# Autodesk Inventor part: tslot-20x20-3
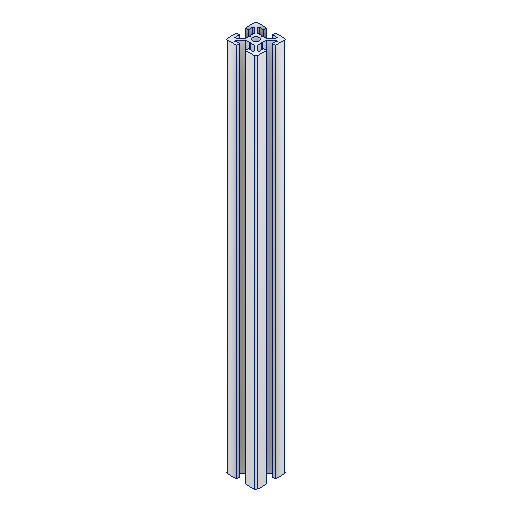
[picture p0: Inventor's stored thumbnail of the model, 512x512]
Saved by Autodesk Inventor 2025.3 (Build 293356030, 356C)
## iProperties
Created: 2025-03
Part Number: tslot-20x20-3
Material: Alluminio 6061
Document SubType Name: Modeling
Designer: Ryzen5700u
Density: 2.7 g/cm^3
Appearance: Alluminio - Piatto
Author: Ryzen5700u
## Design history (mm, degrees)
derived "tslot-20x20-3.ipt"
  sketch "Schizzo1"
    geometry: L1 (-3.761, -16)-(-4.7, -16) reference; L2 (-3.761, -16)-(-0.7, -12.939) reference; L3 (-0.7, -12.939)-(-0.7, -10.52) reference; L4 (-0.4, -10)-(-0.7, -10.52) reference; L5 (-0.4, -10)-(-0.7, -9.48) reference; L6 (-0.7, -7.061)-(-0.7, -9.48) reference; L7 (-3.761, -4)-(-0.7, -7.061) reference; L8 (-3.761, -4)-(-4.7, -4) reference; L9 (-4.7, -4)-(-4.7, -7) reference; L10 (-4.7, -7)-(-6.4, -7) reference; L11 (-6.7, -6.7)-(-6.7, -1) reference; L12 (-5.7, 0)-(0, 0) reference; L13 (0.3, -2)-(0.3, -0.3) reference; L14 (-2.7, -2)-(0.3, -2) reference; L15 (-2.7, -2.939)-(-2.7, -2) reference; L16 (-2.7, -2.939)-(0.361, -6) reference; L17 (0.361, -6)-(2.78, -6) reference; L18 (3.3, -6.3)-(2.78, -6) reference; L19 (3.3, -6.3)-(3.82, -6) reference; L20 (6.239, -6)-(3.82, -6) reference; L21 (9.3, -2.939)-(6.239, -6) reference; L22 (9.3, -2.939)-(9.3, -2) reference; L23 (9.3, -2)-(6.3, -2) reference; L24 (6.3, -2)-(6.3, -0.3) reference; L25 (12.3, 0)-(6.6, 0) reference; L26 (13.3, -6.7)-(13.3, -1) reference; L27 (11.3, -7)-(13, -7) reference; L28 (11.3, -4)-(11.3, -7) reference; L29 (10.361, -4)-(11.3, -4) reference; L30 (10.361, -4)-(7.3, -7.061) reference; L31 (7.3, -7.061)-(7.3, -9.48) reference; L32 (7, -10)-(7.3, -9.48) reference; L33 (7, -10)-(7.3, -10.52) reference; L34 (7.3, -12.939)-(7.3, -10.52) reference; L35 (10.361, -16)-(7.3, -12.939) reference; L36 (10.361, -16)-(11.3, -16) reference; L37 (11.3, -16)-(11.3, -13) reference; L38 (11.3, -13)-(13, -13) reference; L39 (13.3, -13.3)-(13.3, -19) reference; L40 (12.3, -20)-(6.6, -20) reference; L41 (6.3, -18)-(6.3, -19.7) reference; L42 (9.3, -18)-(6.3, -18) reference; L43 (9.3, -17.061)-(9.3, -18) reference; L44 (9.3, -17.061)-(6.239, -14) reference; L45 (6.239, -14)-(3.82, -14) reference; L46 (3.3, -13.7)-(3.82, -14) reference; L47 (3.3, -13.7)-(2.78, -14) reference; L48 (0.361, -14)-(2.78, -14) reference; L49 (-2.7, -17.061)-(0.361, -14) reference; L50 (-2.7, -17.061)-(-2.7, -18) reference; L51 (-2.7, -18)-(0.3, -18) reference; L52 (0.3, -18)-(0.3, -19.7) reference; L53 (-5.7, -20)-(0, -20) reference; L54 (-6.7, -13.3)-(-6.7, -19) reference; L55 (-4.7, -13)-(-6.4, -13) reference; L56 (-4.7, -16)-(-4.7, -13) reference; C1 r 2.1 at (3.3, -10) reference; A1 r 0.3 centre (-6.4, -6.7) between (-6.7, -6.7) and (-6.4, -7) reference; A2 r 1 centre (-5.7, -1) between (-5.7, 0) and (-6.7, -1) reference; A3 r 0.3 centre (0, -0.3) between (0.3, -0.3) and (0, 0) reference; A4 r 0.3 centre (6.6, -0.3) between (6.6, 0) and (6.3, -0.3) reference; A5 r 1 centre (12.3, -1) between (13.3, -1) and (12.3, 0) reference; A6 r 0.3 centre (13, -6.7) between (13, -7) and (13.3, -6.7) reference; A7 r 0.3 centre (13, -13.3) between (13.3, -13.3) and (13, -13) reference; A8 r 1 centre (12.3, -19) between (12.3, -20) and (13.3, -19) reference; A9 r 0.3 centre (6.6, -19.7) between (6.3, -19.7) and (6.6, -20) reference; A10 r 0.3 centre (0, -19.7) between (0, -20) and (0.3, -19.7) reference; A11 r 1 centre (-5.7, -19) between (-6.7, -19) and (-5.7, -20) reference; A12 r 0.3 centre (-6.4, -13.3) between (-6.4, -13) and (-6.7, -13.3) reference; 1 further point
feature "Solido1::tslot-20x20-3.ipt" dims "d0" = 10
tag "Lavorazione contrassegno1"
node "Solido1"
